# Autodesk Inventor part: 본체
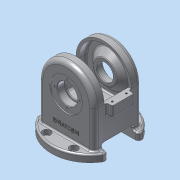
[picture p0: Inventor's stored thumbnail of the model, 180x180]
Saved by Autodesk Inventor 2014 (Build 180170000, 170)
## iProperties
Created: 2024-08
Part Number: 본체
Material: 알루미늄 6061
Document SubType Name: Modeling
Designer: dg
Density: 2.71 g/cm^3
Appearance: 알루미늄 - 평지
Mass: 1203.67 g
Surface Area: 1051.82 cm^2
Volume: 444.159 cm^3
Author: dg
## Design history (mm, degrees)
sketch "스케치1" dims "d0" = 102
  geometry: L1 (-51, 81)-(51, 81); L2 (51, 81)-(51, 0); L3 (51, 0)-(-51, 0); L4 (-51, 0)-(-51, 81); 3 further points
  constraints: 8 end point, 2 coincident, 2 parallel, 1 horizontal, 1 horizontal alignment, 1 midpoint, 1 perpendicular, 2 other
  dimensions: "d1" = 81 distance of L1.end L2.end; "d2" = 102 distance of L2.end L3.end
extrude "돌출1" new body sketch "스케치1" stored distance "d3" = 88; taper "d4" = 0 deg
fillet "모깎기1" dims "d5" = 8
feature "쉘1" dims "d6" = 40, "d7" = 5
sketch "스케치2"
  geometry: L1 (132, 25)-(81, 25); L2 (81, 25)-(81, -25); L3 (81, -25)-(132, -25); L4 (132, -25)-(132, 25); L5 (0, 36)-(0, -36) reference; L6 (81, -36)-(81, -36) reference; L7 (81, -36)-(81, 36) reference; L8 (81, 36)-(81, 36) reference; L9 (81, -36)-(81, 36) reference; L10 (132, -36)-(132, 36) reference; 3 further points
  constraints: 8 end point, 2 midpoint, 2 parallel, 1 horizontal, 1 horizontal alignment, 1 perpendicular
  dimensions: "d8" = 50 distance of L3.end L1.start; "d9" = 132 distance between parallel lines of L5 L4; "d10" = 51 distance of L2.end L3.end
extrude "돌출2" cut sketch "스케치2" stored distance "d11" = 80; taper "d12" = 0 deg
sketch "스케치3"
  geometry: L1 (81, 36)-(81, 44) reference; L2 (81, 44)-(81, 44) reference; L3 (81, 36)-(81, 44) reference; L4 (81, 36)-(81, 36) reference; L5 (81, -36)-(81, -44) reference; L6 (81, -44)-(81, -44) reference; L7 (81, -36)-(81, -44) reference; L8 (81, -36)-(81, -36) reference; L9 (81, 44)-(81, -44); L10 (81, 39)-(124, 39) reference; L11 (124, -39)-(81, -39) reference; L12 (114.5, 39)-(102.5, 27); L13 (102.5, 27)-(81, 27); L14 (127, 25)-(127, 36) reference; L15 (114.5, -39)-(102.5, -27); L16 (102.5, -27)-(81, -27); L17 (114.5, 39)-(81, 39); L18 (114.5, -39)-(81, -39); L19 (81, 27)-(81, 39); L20 (81, -27)-(81, -39); L21 (81, -25)-(81, -25) reference; L22 (81, -36)-(81, -25) reference; L23 (81, -36)-(81, -36) reference; L24 (81, -36)-(81, -25) reference; 1 further point
  constraints: 18 end point, 3 collinear, 3 perpendicular, 2 point on line
  dimensions: "d15" = 12 distance between parallel lines of L10 L13; "d113" = 67 diameter of L12.start L9; "d114" = 12 distance between parallel lines of L11 L16; "d116" = 67 diameter of L15.start L9; "d120" = 45 deg angle of L14 L12; "d121" = 135 deg angle of L9 L15
revolve "회전1" sketch "스케치3" stored, may be unused: angle "d16" = 90 deg
sketch "스케치4"
  geometry: C1 r 16 at (0, 81); A1 r 43 centre (0, 81) between (43, 81) and (-43, 81) reference; 1 further point
  constraints: 1 centre point, 1 coincident
  dimensions: "d17" = 32 diameter of C1
extrude "돌출3" cut sketch "스케치4" stored distance "d18" = 0; taper "d19" = 0 deg
sketch "스케치5"
  geometry: C1 r 16 at (0, 81) reference; C2 r 30 at (0, 81); A1 r 43 centre (0, 81) between (43, 81) and (-43, 81) reference; 1 further point
  constraints: 1 centre point, 1 coincident
  dimensions: "d20" = 60 diameter of C2
extrude "돌출4" cut sketch "스케치5" distance "d21" = 2; taper "d22" = 0 deg
sketch "스케치6"
  geometry: C1 r 30 at (0, 0) reference; A1 r 23 centre (0, 0) between (23, 0) and (0, 23); 3 further points
  constraints: 4 point on circle, 1 centre point, 1 coincident
  dimensions: "d23" = 46 diameter of A1
hole "구멍1" sketch "스케치6" at (23, 0), (0, 23), (-23, 0), (0, -23) diameter "d24" = 3.242; stored, may be unused: countersink angle "d28" = 90 deg, drill point angle "d30" = 118 deg; dims "d25" = 8, "d26" = 4, "d27" = 2, "d29" = 10
sketch "스케치7"
  geometry: L1 (86, 0)-(0, 0) reference; L2 (94, 80)-(94, 8) reference; L3 (0, 88)-(86, 88) reference; L4 (-8, 80)-(-8, 8) reference; C1 r 71 at (43, 44); A1 r 8 centre (0, 8) between (-8, 8) and (0, 0) reference; A2 r 8 centre (86, 8) between (86, 0) and (94, 8) reference; A3 r 8 centre (86, 80) between (94, 80) and (86, 88) reference; A4 r 8 centre (0, 80) between (0, 88) and (-8, 80) reference; 1 further point
  constraints: 1 centre point, 1 coincident
  dimensions: "d31" = 142 diameter of C1
extrude "돌출5" join sketch "스케치7" distance "d32" = 13; taper "d33" = 0 deg
sketch "스케치8"
  geometry: L1 (19, 28)-(0, 28); L2 (0, 28)-(0, -28); L3 (0, -28)-(19, -28); L4 (19, -28)-(19, 28); 3 further points
  constraints: 8 end point, 2 midpoint, 2 parallel, 1 coincident, 1 horizontal, 1 horizontal alignment, 1 perpendicular
  dimensions: "d34" = 19 distance of L2.end L3.end; "d35" = 56 distance of L3.end L1.start
extrude "돌출6" cut sketch "스케치8" stored distance "d36" = 200; taper "d37" = 0 deg
sketch "스케치9"
  geometry: C1 r 11 at (51, 28); 1 further point
  constraints: 1 centre point, 1 coincident
  dimensions: "d38" = 22 diameter of C1
extrude "돌출7" cut sketch "스케치9" distance "d39" = 200; taper "d40" = 0 deg
sketch "스케치10"
  geometry: C1 r 11 at (51, 28) reference; C2 r 14 at (51, 28)
  constraints: 1 centre point, 1 coincident
  dimensions: "d41" = 28 diameter of C2
extrude "돌출8" cut sketch "스케치10" distance "d42" = 18; taper "d43" = 0 deg
sketch "스케치12"
  geometry: L1 (5, 0)-(5, -50) reference; L2 (0, -50)-(5, -50) reference; L3 (-46, -25)-(-46, 69.854); L4 (5, -5)-(15, -5); L5 (15, -5)-(15, -45); L6 (15, -45)-(5, -45); L7 (5, -45)-(5, -5); L8 (-107, -5)-(-107, -45); L9 (-97, -5)-(-107, -5); L10 (-97, 0)-(-97, -50); L11 (-107, -45)-(-97, -45); L12 (-97, -45)-(-97, -5); 1 further point
  constraints: 20 end point, 6 symmetric about line, 2 parallel, 2 perpendicular, 2 point on line, 1 horizontal, 1 horizontal alignment, 1 midpoint
  dimensions: "d52" = 40 distance of L4.end L5.end; "d53" = 61 distance between parallel lines of L3 L5
extrude "돌출9" join sketch "스케치12" distance "d54" = 20; taper "d55" = 0 deg
sketch "스케치13"
  geometry: L1 (-100, -12)-(8, -12); L2 (8, -12)-(8, -38); L3 (8, -38)-(-100, -38); L4 (-100, -38)-(-100, -12); 7 further points
  constraints: 8 end point, 4 coincident, 2 midpoint, 2 parallel, 1 horizontal, 1 horizontal alignment, 1 perpendicular, 1 vertical alignment
  dimensions: "d56" = 108 distance of L2.end L3.end; "d57" = 26 distance of L1.end L2.end
hole "구멍3" sketch "스케치13" at (8, -12), (8, -38), (-100, -38), (-100, -12) diameter "d58" = 3.242; stored, may be unused: countersink angle "d62" = 90 deg, drill point angle "d64" = 118 deg; dims "d59" = 8, "d60" = 4, "d61" = 2, "d63" = 10
sketch "스케치14"
  geometry: C1 r 16 at (0, 0) reference; C2 r 30 at (0, 0) reference; C3 r 18.5 at (0, 0); 1 further point
  constraints: 1 centre point, 1 coincident
  dimensions: "d65" = 37 diameter of C3
extrude "돌출10" cut sketch "스케치14" distance "d66" = 13; taper "d67" = 0 deg
sketch "스케치15"
  geometry: C1 r 16 at (0, 0) reference; C2 r 30 at (0, 0) reference; C3 r 18.5 at (0, 0); 1 further point
  constraints: 1 centre point, 1 coincident
  dimensions: "d68" = 37 diameter of C3
extrude "돌출11" cut sketch "스케치15" distance "d69" = 13; taper "d70" = 0 deg
sketch "스케치16"
  geometry: L1 (18, 11)-(68, 11); L2 (68, 11)-(68, -99); L3 (68, -99)-(18, -99); L4 (18, -99)-(18, 11); A1 r 71 centre (43, -44) between (-22.246, -72) and (108.246, -72) reference; 6 further points
  constraints: 8 end point, 4 coincident, 2 midpoint, 2 parallel, 1 horizontal, 1 horizontal alignment, 1 perpendicular, 1 vertical alignment
  dimensions: "d71" = 50 distance of L2.end L3.end; "d72" = 110 distance of L1.end L2.end
hole "구멍4" sketch "스케치16" at (18, 11), (68, 11), (18, -99), (68, -99) diameter "d73" = 9; stored, may be unused: countersink angle "d77" = 90 deg, drill point angle "d79" = 118 deg; dims "d74" = 8, "d75" = 15, "d76" = 8.8, "d78" = 20
fillet "모깎기2" dims "d80" = 6
fillet "모깎기3" dims "d81" = 0.3
fillet "모깎기4" dims "d82" = 3
fillet "모깎기5" dims "d83" = 3
fillet "모깎기6" dims "d84" = 3
fillet "모깎기7" dims "d85" = 3
chamfer "모따기1" distance "d86" = 1; stored, may be unused: second distance "d87" = 2, angle "d88" = 45 deg
sketch "스케치17"
  geometry: L1 (-35.672, 35)-(35.672, 35); L2 (35.672, 35)-(35.672, 25); L3 (35.672, 25)-(-35.672, 25); L4 (-35.672, 25)-(-35.672, 35); L5 (60.512, 0)-(-60.512, 0) reference; L6 (61.399, 0)-(55.399, 0) reference; 4 further points
  constraints: 2 midpoint, 1 vertical alignment, 2 other
  dimensions: "d92" = 30 vertical distance of L6.start point (0, 30)
feature "엠보싱1" sketch "스케치17" dims "d93" = 0.5, "d94" = 0
sketch "스케치19"
  geometry: C1 r 30 at (0, 0); A1 r 71 centre (0, 0) between (-60.512, -37.138) and (60.512, -37.138) reference
  constraints: 1 centre point, 1 coincident
  dimensions: "d98" = 60 diameter of C1
extrude "돌출13" cut sketch "스케치19" distance "d99" = 22; taper "d100" = 0 deg
fillet "모깎기8" dims "d101" = 3
sketch "스케치20"
  geometry: C1 r 30 at (0, 0) reference; A1 r 23 centre (0, 0) between (23, 0) and (0, 23); 2 further points
  constraints: 4 point on circle, 1 centre point, 1 coincident
  dimensions: "d102" = 46 diameter of A1
hole "구멍5" sketch "스케치20" at (23, 0), (0, 23), (-23, 0), (0, -23) diameter "d103" = 3.242; stored, may be unused: countersink angle "d107" = 90 deg, drill point angle "d109" = 118 deg; dims "d104" = 8, "d105" = 4, "d106" = 2, "d108" = 10
fillet "모깎기9" dims "d110" = 3
chamfer "모따기2" distance "d117" = 1; stored, may be unused: second distance "d118" = 2, angle "d119" = 45 deg
node "솔리드1"
mirror "대칭1"
node "투영된 루프1"
node "투영된 루프2"
node "투영된 루프3"
node "투영된 루프4"
